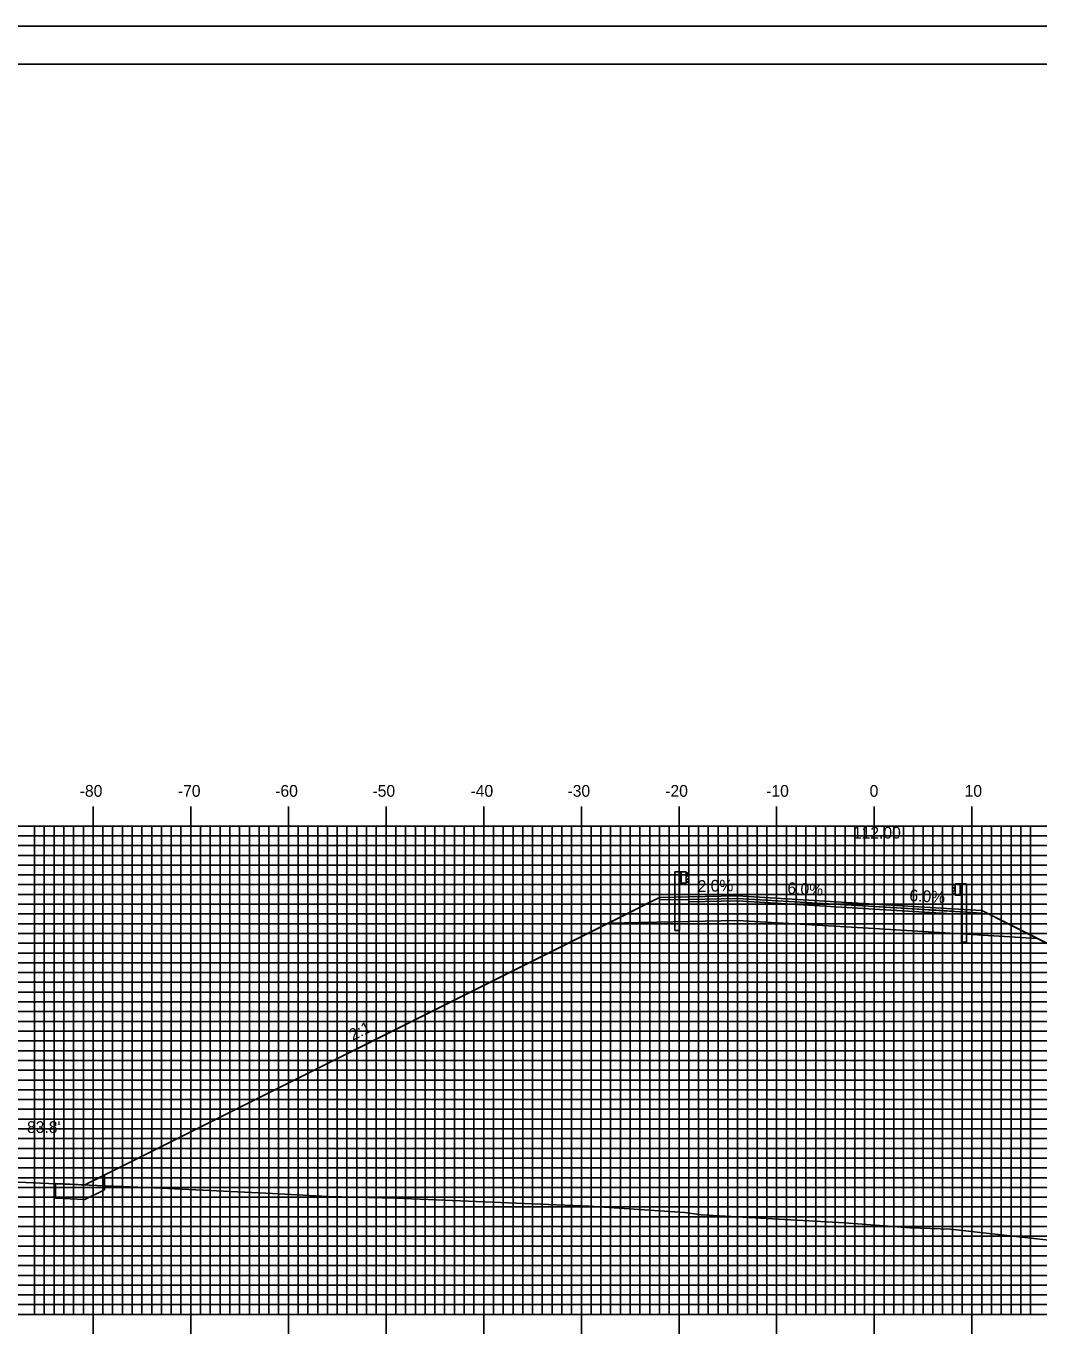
# Model space of a CAD drawing. Extents: x 857897 to 858240, y 364765 to 364985.
# Drawn here: x 857976 to 858079.7, y 364850.8 to 364985.2 of the extents above; entities that cross this region are included whole.
import ezdxf

# ---------------------------------------------------------------- set-up
doc = ezdxf.new("R2010")
doc.units = 0
for name, color, linetype in [('ANNOTATION', 7, 'Continuous'), ('BORDER', 7, 'Continuous'), ('D_Guardrail_Beam_Lt', 7, 'Continuous'), ('D_Guardrail_Beam_Rt', 7, 'Continuous'), ('D_Roadway_Centerline', 7, 'Continuous'), ('D_Roadway_Centerline_Text', 7, 'Continuous'), ('D_Roadway_Edge_Shoulder', 7, 'Continuous'), ('D_Roadway_Edge_TW', 7, 'Continuous'), ('D_Roadway_FinishedGrade', 7, 'Continuous'), ('D_Roadway_Pavement', 7, 'Continuous'), ('D_Roadway_SlopeLines', 7, 'Continuous'), ('D_Roadway_SubGrade', 7, 'Continuous'), ('D_Text_Standard', 7, 'Continuous'), ('H_V ANNOTATION', 7, 'Continuous'), ('MAJOR', 7, 'Continuous'), ('MINOR', 7, 'Continuous'), ('PLOT BOUNDARY', 7, 'Continuous'), ('S_Roadway_Centerline', 7, 'Continuous')]:
    doc.layers.add(name, color=color, linetype=linetype)

msp = doc.modelspace()

# ---------------------------------------------------------------- linework, layer by layer
at = {"layer": 'BORDER'}
msp.add_lwpolyline([(857913.22, 364771.3), (858233.22, 364771.3), (858233.22, 364981.3), (857913.22, 364981.3)], close=True, dxfattribs=at)
at = {"layer": 'D_Guardrail_Beam_Lt'}
for p, q in [((858042.39, 364898.62), (858042.39, 364892.62)), ((858042.86, 364898.62), (858042.39, 364898.62)), ((858043.55, 364898.62), (858042.86, 364898.62)), ((858042.86, 364898.62), (858042.86, 364897.46)), ((858042.86, 364897.46), (858043.55, 364897.46)), ((858042.88, 364892.62), (858042.88, 364897.46)), ((858042.92, 364898.62), (858042.92, 364897.46)), ((858043.03, 364898.62), (858043.03, 364897.46)), ((858043.55, 364897.46), (858043.55, 364898.62)), ((858043.55, 364898.54), (858043.62, 364898.52)), ((858043.55, 364898.07), (858043.55, 364898)), ((858043.62, 364897.55), (858043.55, 364897.54)), ((858043.78, 364898.27), (858043.59, 364898.14)), ((858043.59, 364897.94), (858043.78, 364897.8)), ((858043.64, 364898.52), (858043.78, 364898.42)), ((858043.78, 364897.66), (858043.64, 364897.56)), ((858042.88, 364892.62), (858042.39, 364892.62))]:
    msp.add_line(p, q, dxfattribs=at)
for centre, major_axis, start_param, end_param in [((858043.63, 364898.07), (-0.0789, 0), 5.323254, 6.283185), ((858043.63, 364898), (-0.0789, 0), 6.283185, 7.243116), ((858043.62, 364898.48), (0.0417, 0), 0.959931, 1.376053), ((858043.62, 364897.59), (0.0417, 0), 4.907132, 5.323254), ((858043.73, 364898.35), (0.0877, 0), 5.323254, 7.243116), ((858043.73, 364897.73), (0.0877, 0), 5.323254, 7.243116)]:
    msp.add_ellipse(centre, major_axis=major_axis, ratio=0.995501, start_param=start_param, end_param=end_param, dxfattribs=at)
at = {"layer": 'D_Guardrail_Beam_Rt'}
for p, q in [((858071.09, 364897.4), (858071.78, 364897.4)), ((858071.09, 364896.24), (858071.09, 364897.4)), ((858071.61, 364897.4), (858071.61, 364896.24)), ((858071.72, 364897.4), (858071.72, 364896.24)), ((858071.78, 364897.4), (858072.25, 364897.4)), ((858071.78, 364897.4), (858071.78, 364896.24)), ((858072.25, 364897.4), (858072.25, 364891.4)), ((858071, 364897.3), (858070.86, 364897.2)), ((858070.86, 364897.05), (858071.05, 364896.92)), ((858071.05, 364896.72), (858070.86, 364896.58)), ((858070.86, 364896.44), (858071, 364896.34)), ((858071.09, 364897.32), (858071.02, 364897.3)), ((858071.02, 364896.33), (858071.09, 364896.32)), ((858071.09, 364896.85), (858071.09, 364896.78)), ((858071.78, 364896.24), (858071.09, 364896.24)), ((858071.76, 364891.4), (858071.76, 364896.24)), ((858071.76, 364891.4), (858072.25, 364891.4))]:
    msp.add_line(p, q, dxfattribs=at)
for centre, major_axis, start_param, end_param in [((858070.91, 364897.13), (-0.0877, 0), 5.323254, 7.243116), ((858070.91, 364896.51), (-0.0877, 0), 5.323254, 7.243116), ((858071.03, 364897.26), (-0.0417, 0), 4.907132, 5.323254), ((858071.03, 364896.37), (-0.0417, 0), 0.959931, 1.376053), ((858071.01, 364896.85), (0.0789, 0), 0, 0.959931), ((858071.01, 364896.78), (0.0789, 0), 5.323254, 6.283185)]:
    msp.add_ellipse(centre, major_axis=major_axis, ratio=0.995501, start_param=start_param, end_param=end_param, dxfattribs=at)
at = {"layer": 'D_Roadway_Centerline'}
msp.add_lwpolyline([(857981.97, 364866.56), (858035.61, 364893.37), (858040.82, 364895.98), (858043.82, 364896.04), (858048.82, 364896.14), (858062.82, 364895.3), (858070.82, 364894.82), (858073.82, 364894.64), (858079.5, 364891.8), (858136.93, 364863.09)], dxfattribs=at)
at = {"layer": 'D_Roadway_Edge_Shoulder'}
for points in [[(858048.82, 364896.14), (858043.82, 364896.04), (858043.82, 364896.04), (858040.82, 364895.98), (858040.82, 364895.73), (858043.82, 364895.79), (858048.82, 364895.89)], [(858062.82, 364895.3), (858070.82, 364894.82), (858070.82, 364894.82), (858073.82, 364894.64), (858073.82, 364894.39), (858062.82, 364895.05)]]:
    msp.add_lwpolyline(points, close=True, dxfattribs=at)
at = {"layer": 'D_Roadway_Edge_TW'}
msp.add_lwpolyline([(858048.82, 364896.14), (858062.82, 364895.3), (858062.82, 364895.05), (858048.82, 364895.89)], close=True, dxfattribs=at)
at = {"layer": 'D_Roadway_FinishedGrade'}
for points in [[(857983.97, 364867.56), (857983.97, 364866.06), (857981.97, 364865.06), (857978.97, 364865.19), (857978.97, 364866.69), (857981.97, 364866.56)], [(857978.97, 364866.69), (857978.97, 364865.19), (857981.97, 364865.06), (857983.97, 364866.06), (857983.97, 364867.56), (857981.97, 364866.56)]]:
    msp.add_lwpolyline(points, close=True, dxfattribs=at)
at = {"layer": 'D_Roadway_Pavement'}
for points in [[(858048.82, 364895.89), (858043.82, 364895.79), (858043.82, 364895.54), (858048.82, 364895.64)], [(858048.82, 364895.89), (858062.82, 364895.05), (858062.82, 364894.8), (858048.82, 364895.64)]]:
    msp.add_lwpolyline(points, close=True, dxfattribs=at)
for points in [[(858062.82, 364895.05), (858062.82, 364894.8)], [(858062.82, 364895.05), (858062.82, 364894.8)], [(858062.82, 364895.05), (858062.82, 364894.8)], [(858062.82, 364895.05), (858070.82, 364894.57), (858070.82, 364894.32), (858062.82, 364894.8)]]:
    msp.add_lwpolyline(points, dxfattribs=at)
at = {"layer": 'D_Roadway_SlopeLines'}
msp.add_line((858040.82, 364895.98), (858038.82, 364894.98), dxfattribs=at)
for points in [[(858040.82, 364895.98), (857981.97, 364866.56)], [(858073.82, 364894.64), (858136.93, 364863.09)]]:
    msp.add_lwpolyline(points, dxfattribs=at)
at = {"layer": 'D_Roadway_SubGrade'}
for points in [[(858048.82, 364895.64), (858043.82, 364895.54), (858043.82, 364895.79), (858040.82, 364895.73), (858040.82, 364895.98), (858035.61, 364893.37), (858048.82, 364893.64)], [(858048.82, 364895.64), (858062.82, 364894.8), (858062.82, 364892.8), (858048.82, 364893.64)], [(858062.82, 364894.8), (858062.82, 364895.05), (858073.82, 364894.39), (858073.82, 364894.64), (858079.5, 364891.8), (858062.82, 364892.8)]]:
    msp.add_lwpolyline(points, close=True, dxfattribs=at)
at = {"layer": 'MAJOR'}
for p, q in [((857982.82, 364905.31), (857982.82, 364903.3)), ((857992.82, 364905.31), (857992.82, 364903.3)), ((858002.82, 364905.31), (858002.82, 364903.3)), ((858012.82, 364905.31), (858012.82, 364903.3)), ((858022.82, 364905.31), (858022.82, 364903.3)), ((858032.82, 364905.31), (858032.82, 364903.3)), ((858042.82, 364905.31), (858042.82, 364903.3)), ((858052.82, 364905.31), (858052.82, 364903.3)), ((858062.82, 364905.31), (858062.82, 364903.3)), ((858072.82, 364905.31), (858072.82, 364903.3)), ((857922.82, 364903.3), (858202.82, 364903.3)), ((857922.82, 364903.3), (858202.82, 364903.3)), ((857982.82, 364853.3), (857982.82, 364903.3)), ((857992.82, 364853.3), (857992.82, 364903.3)), ((858002.82, 364853.3), (858002.82, 364903.3)), ((858012.82, 364853.3), (858012.82, 364903.3)), ((858022.82, 364853.3), (858022.82, 364903.3)), ((858032.82, 364853.3), (858032.82, 364903.3)), ((858042.82, 364853.3), (858042.82, 364903.3)), ((858052.82, 364853.3), (858052.82, 364903.3)), ((858062.82, 364853.3), (858062.82, 364903.3)), ((858072.82, 364853.3), (858072.82, 364903.3)), ((857922.82, 364898.3), (858202.82, 364898.3)), ((857922.82, 364893.3), (858202.82, 364893.3)), ((857922.82, 364888.3), (858202.82, 364888.3)), ((857922.82, 364883.3), (858202.82, 364883.3)), ((857922.82, 364878.3), (858202.82, 364878.3)), ((857922.82, 364873.3), (858202.82, 364873.3)), ((857922.82, 364868.3), (858202.82, 364868.3)), ((857922.82, 364863.3), (858202.82, 364863.3)), ((857922.82, 364858.3), (858202.82, 364858.3)), ((857922.82, 364853.3), (858202.82, 364853.3)), ((857922.82, 364853.3), (858202.82, 364853.3)), ((857982.82, 364851.3), (857982.82, 364853.3)), ((857992.82, 364851.3), (857992.82, 364853.3)), ((858002.82, 364851.3), (858002.82, 364853.3)), ((858012.82, 364851.3), (858012.82, 364853.3)), ((858022.82, 364851.3), (858022.82, 364853.3)), ((858032.82, 364851.3), (858032.82, 364853.3)), ((858042.82, 364851.3), (858042.82, 364853.3)), ((858052.82, 364851.3), (858052.82, 364853.3)), ((858062.82, 364851.3), (858062.82, 364853.3)), ((858072.82, 364851.3), (858072.82, 364853.3))]:
    msp.add_line(p, q, dxfattribs=at)
at = {"layer": 'MINOR'}
for p, q in [((857976.82, 364853.3), (857976.82, 364903.3)), ((857977.82, 364853.3), (857977.82, 364903.3)), ((857978.82, 364853.3), (857978.82, 364903.3)), ((857979.82, 364853.3), (857979.82, 364903.3)), ((857980.82, 364853.3), (857980.82, 364903.3)), ((857981.82, 364853.3), (857981.82, 364903.3)), ((857983.82, 364853.3), (857983.82, 364903.3)), ((857984.82, 364853.3), (857984.82, 364903.3)), ((857985.82, 364853.3), (857985.82, 364903.3)), ((857986.82, 364853.3), (857986.82, 364903.3)), ((857987.82, 364853.3), (857987.82, 364903.3)), ((857988.82, 364853.3), (857988.82, 364903.3)), ((857989.82, 364853.3), (857989.82, 364903.3)), ((857990.82, 364853.3), (857990.82, 364903.3)), ((857991.82, 364853.3), (857991.82, 364903.3)), ((857993.82, 364853.3), (857993.82, 364903.3)), ((857994.82, 364853.3), (857994.82, 364903.3)), ((857995.82, 364853.3), (857995.82, 364903.3)), ((857996.82, 364853.3), (857996.82, 364903.3)), ((857997.82, 364853.3), (857997.82, 364903.3)), ((857998.82, 364853.3), (857998.82, 364903.3)), ((857999.82, 364853.3), (857999.82, 364903.3)), ((858000.82, 364853.3), (858000.82, 364903.3)), ((858001.82, 364853.3), (858001.82, 364903.3)), ((858003.82, 364853.3), (858003.82, 364903.3)), ((858004.82, 364853.3), (858004.82, 364903.3)), ((858005.82, 364853.3), (858005.82, 364903.3)), ((858006.82, 364853.3), (858006.82, 364903.3)), ((858007.82, 364853.3), (858007.82, 364903.3)), ((858008.82, 364853.3), (858008.82, 364903.3)), ((858009.82, 364853.3), (858009.82, 364903.3)), ((858010.82, 364853.3), (858010.82, 364903.3)), ((858011.82, 364853.3), (858011.82, 364903.3)), ((858013.82, 364853.3), (858013.82, 364903.3)), ((858014.82, 364853.3), (858014.82, 364903.3)), ((858015.82, 364853.3), (858015.82, 364903.3)), ((858016.82, 364853.3), (858016.82, 364903.3)), ((858017.82, 364853.3), (858017.82, 364903.3)), ((858018.82, 364853.3), (858018.82, 364903.3)), ((858019.82, 364853.3), (858019.82, 364903.3)), ((858020.82, 364853.3), (858020.82, 364903.3)), ((858021.82, 364853.3), (858021.82, 364903.3)), ((858023.82, 364853.3), (858023.82, 364903.3)), ((858024.82, 364853.3), (858024.82, 364903.3)), ((858025.82, 364853.3), (858025.82, 364903.3)), ((858026.82, 364853.3), (858026.82, 364903.3)), ((858027.82, 364853.3), (858027.82, 364903.3)), ((858028.82, 364853.3), (858028.82, 364903.3)), ((858029.82, 364853.3), (858029.82, 364903.3)), ((858030.82, 364853.3), (858030.82, 364903.3)), ((858031.82, 364853.3), (858031.82, 364903.3)), ((858033.82, 364853.3), (858033.82, 364903.3)), ((858034.82, 364853.3), (858034.82, 364903.3)), ((858035.82, 364853.3), (858035.82, 364903.3)), ((858036.82, 364853.3), (858036.82, 364903.3)), ((858037.82, 364853.3), (858037.82, 364903.3)), ((858038.82, 364853.3), (858038.82, 364903.3)), ((858039.82, 364853.3), (858039.82, 364903.3)), ((858040.82, 364853.3), (858040.82, 364903.3)), ((858041.82, 364853.3), (858041.82, 364903.3)), ((858043.82, 364853.3), (858043.82, 364903.3)), ((858044.82, 364853.3), (858044.82, 364903.3)), ((858045.82, 364853.3), (858045.82, 364903.3)), ((858046.82, 364853.3), (858046.82, 364903.3)), ((858047.82, 364853.3), (858047.82, 364903.3)), ((858048.82, 364853.3), (858048.82, 364903.3)), ((858049.82, 364853.3), (858049.82, 364903.3)), ((858050.82, 364853.3), (858050.82, 364903.3)), ((858051.82, 364853.3), (858051.82, 364903.3)), ((858053.82, 364853.3), (858053.82, 364903.3)), ((858054.82, 364853.3), (858054.82, 364903.3)), ((858055.82, 364853.3), (858055.82, 364903.3)), ((858056.82, 364853.3), (858056.82, 364903.3)), ((858057.82, 364853.3), (858057.82, 364903.3)), ((858058.82, 364853.3), (858058.82, 364903.3)), ((858059.82, 364853.3), (858059.82, 364903.3)), ((858060.82, 364853.3), (858060.82, 364903.3)), ((858061.82, 364853.3), (858061.82, 364903.3)), ((858063.82, 364853.3), (858063.82, 364903.3)), ((858064.82, 364853.3), (858064.82, 364903.3)), ((858065.82, 364853.3), (858065.82, 364903.3)), ((858066.82, 364853.3), (858066.82, 364903.3)), ((858067.82, 364853.3), (858067.82, 364903.3)), ((858068.82, 364853.3), (858068.82, 364903.3)), ((858069.82, 364853.3), (858069.82, 364903.3)), ((858070.82, 364853.3), (858070.82, 364903.3)), ((858071.82, 364853.3), (858071.82, 364903.3)), ((858073.82, 364853.3), (858073.82, 364903.3)), ((858074.82, 364853.3), (858074.82, 364903.3)), ((858075.82, 364853.3), (858075.82, 364903.3)), ((858076.82, 364853.3), (858076.82, 364903.3)), ((858077.82, 364853.3), (858077.82, 364903.3)), ((858078.82, 364853.3), (858078.82, 364903.3)), ((857922.82, 364902.3), (858202.82, 364902.3)), ((857922.82, 364901.3), (858202.82, 364901.3)), ((857922.82, 364900.3), (858202.82, 364900.3)), ((857922.82, 364899.3), (858202.82, 364899.3)), ((857922.82, 364897.3), (858202.82, 364897.3)), ((857922.82, 364896.3), (858202.82, 364896.3)), ((857922.82, 364895.3), (858202.82, 364895.3)), ((857922.82, 364894.3), (858202.82, 364894.3)), ((857922.82, 364892.3), (858202.82, 364892.3)), ((857922.82, 364891.3), (858202.82, 364891.3)), ((857922.82, 364890.3), (858202.82, 364890.3)), ((857922.82, 364889.3), (858202.82, 364889.3)), ((857922.82, 364887.3), (858202.82, 364887.3)), ((857922.82, 364886.3), (858202.82, 364886.3)), ((857922.82, 364885.3), (858202.82, 364885.3)), ((857922.82, 364884.3), (858202.82, 364884.3)), ((857922.82, 364882.3), (858202.82, 364882.3)), ((857922.82, 364881.3), (858202.82, 364881.3)), ((857922.82, 364880.3), (858202.82, 364880.3)), ((857922.82, 364879.3), (858202.82, 364879.3)), ((857922.82, 364877.3), (858202.82, 364877.3)), ((857922.82, 364876.3), (858202.82, 364876.3)), ((857922.82, 364875.3), (858202.82, 364875.3)), ((857922.82, 364874.3), (858202.82, 364874.3)), ((857922.82, 364872.3), (858202.82, 364872.3)), ((857922.82, 364871.3), (858202.82, 364871.3)), ((857922.82, 364870.3), (858202.82, 364870.3)), ((857922.82, 364869.3), (858202.82, 364869.3)), ((857922.82, 364867.3), (858202.82, 364867.3)), ((857922.82, 364866.3), (858202.82, 364866.3)), ((857922.82, 364865.3), (858202.82, 364865.3)), ((857922.82, 364864.3), (858202.82, 364864.3)), ((857922.82, 364862.3), (858202.82, 364862.3)), ((857922.82, 364861.3), (858202.82, 364861.3)), ((857922.82, 364860.3), (858202.82, 364860.3)), ((857922.82, 364859.3), (858202.82, 364859.3)), ((857922.82, 364857.3), (858202.82, 364857.3)), ((857922.82, 364856.3), (858202.82, 364856.3)), ((857922.82, 364855.3), (858202.82, 364855.3)), ((857922.82, 364854.3), (858202.82, 364854.3))]:
    msp.add_line(p, q, dxfattribs=at)
at = {"layer": 'PLOT BOUNDARY'}
msp.add_lwpolyline([(857897.03, 364765.18), (858237.03, 364765.18), (858237.03, 364985.18), (857897.03, 364985.18)], close=True, dxfattribs=at)
at = {"layer": 'S_Roadway_Centerline'}
msp.add_lwpolyline([(857922.82, 364869.53), (857923.95, 364869.52), (857939.13, 364868.49), (857945.1, 364868.38), (857951.57, 364868.07), (857960.69, 364867.5), (857968.94, 364867.12), (857977.46, 364866.75), (857989.04, 364866.25), (858001.2, 364865.69), (858006.87, 364865.36), (858013.81, 364865.2), (858033.57, 364864.37), (858043.41, 364863.75), (858045.08, 364863.5), (858047.56, 364863.36), (858059.78, 364862.66), (858066.49, 364862.17), (858070.62, 364862.03), (858082.49, 364860.71)], dxfattribs=at)

# ---------------------------------------------------------------- texts
at = {"layer": 'ANNOTATION'}
for s, rotation, p in [('2.0%', 1.1458, (858044.74, 364896.55)), ('6.0%', 356.5664, (858053.89, 364896.37)), ('6.0%', 356.5504, (858066.39, 364895.62)), ('2:1', 26.5651, (858009.41, 364881.29))]:
    msp.add_text(s, height=1.2, rotation=rotation, dxfattribs=at).set_placement(p)
at = {"layer": 'D_Roadway_Centerline_Text'}
msp.add_text('112.00', height=1.2, dxfattribs=at).set_placement((858060.63, 364902.02))
at = {"layer": 'D_Text_Standard'}
msp.add_text("83.8'", height=1.2, dxfattribs=at).set_placement((857976.05, 364871.88))
at = {"layer": 'H_V ANNOTATION'}
for s, p in [('-80', (857981.45, 364906.3)), ('-70', (857991.5, 364906.3)), ('-60', (858001.47, 364906.3)), ('-50', (858011.43, 364906.3)), ('-40', (858021.47, 364906.3)), ('-30', (858031.4, 364906.3)), ('-20', (858041.41, 364906.3)), ('-10', (858051.75, 364906.3)), ('0', (858062.34, 364906.3)), ('10', (858072.07, 364906.3))]:
    msp.add_text(s, height=1.2, dxfattribs=at).set_placement(p)

doc.saveas('drawing.dxf')
